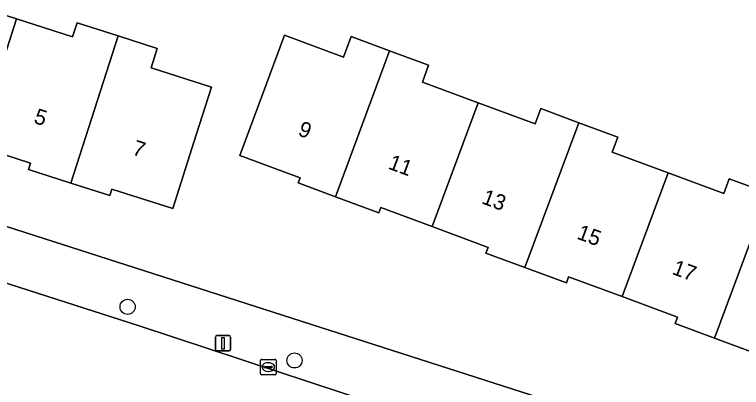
# Model space of a CAD drawing. Extents: x 163266 to 164362, y 381528 to 382286.
# Drawn here: x 163801.11 to 163848.12, y 382001.05 to 382025.18 of the extents above; entities that cross this region are included whole.
import ezdxf

# ---------------------------------------------------------------- set-up
doc = ezdxf.new("R2010")
doc.units = 0
for name, color, linetype in [('IMGEO_Boom', 7, 'Continuous'), ('IMGEO_Erf', 7, 'Continuous'), ('IMGEO_Kolk', 7, 'Continuous'), ('IMGEO_Lichtmast', 7, 'Continuous'), ('IMGEO_Pand', 7, 'Continuous'), ('IMGEO_Pand_nummerreeks', 7, 'Continuous'), ('IMGEO_Rijbaan_lokaal_open', 7, 'Continuous'), ('IMGEO_Voetpad_open', 7, 'Continuous')]:
    doc.layers.add(name, color=color, linetype=linetype)

msp = doc.modelspace()

# ---------------------------------------------------------------- linework, layer by layer
at = {"layer": 'IMGEO_Boom'}
for centre in [(163808.427, 382006.269), (163819.217, 382002.805)]:
    msp.add_circle(centre, 0.489, dxfattribs=at)
at = {"layer": 'IMGEO_Erf'}
for points in [[(163797.866, 382025.977), (163801.242, 382024.894), (163804.871, 382023.73), (163805.164, 382024.644), (163807.816, 382023.794), (163810.342, 382022.984), (163809.942, 382021.739), (163813.86, 382020.482), (163812.869, 382017.392), (163811.342, 382012.63), (163807.414, 382013.889), (163807.279, 382013.469), (163804.764, 382014.276), (163802.025, 382015.154), (163802.156, 382015.564), (163798.615, 382016.7)], [(163848.94, 382003.298), (163846.386, 382004.246), (163843.828, 382005.195), (163843.981, 382005.607), (163840.404, 382006.934), (163836.95, 382008.216), (163836.801, 382007.815), (163834.119, 382008.81), (163831.601, 382009.745), (163831.739, 382010.119), (163828.123, 382011.461), (163824.808, 382012.691), (163824.681, 382012.35), (163821.861, 382013.396), (163819.459, 382014.287), (163819.584, 382014.625), (163815.693, 382016.069), (163817.433, 382020.757), (163818.577, 382023.841), (163822.389, 382022.426), (163822.884, 382023.761), (163825.374, 382022.837), (163827.894, 382021.902), (163827.489, 382020.809), (163831.103, 382019.468), (163834.775, 382018.106), (163835.142, 382019.096), (163837.607, 382018.181), (163840.128, 382017.246), (163839.766, 382016.272), (163843.38, 382014.931), (163846.979, 382013.596), (163847.335, 382014.558), (163849.873, 382013.616)], [(163784.545, 382016.624), (163836.291, 382000), (163875.242, 381987.433)]]:
    msp.add_lwpolyline(points, dxfattribs=at)
at = {"layer": 'IMGEO_Kolk'}
for p, q in [((163817.028, 382001.948), (163817.028, 382002.8)), ((163817.103, 382002.874), (163817.955, 382002.874)), ((163817.516, 382002.654), (163817.541, 382002.654)), ((163818.029, 382002.8), (163818.029, 382001.948)), ((163817.287, 382002.368), (163817.287, 382002.38)), ((163817.725, 382002.331), (163817.327, 382002.331)), ((163817.33, 382002.417), (163817.728, 382002.417)), ((163817.539, 382002.094), (163817.514, 382002.094)), ((163817.771, 382002.38), (163817.771, 382002.368)), ((163817.955, 382001.874), (163817.103, 382001.874))]:
    msp.add_line(p, q, dxfattribs=at)
for points in [[(163817.028, 382001.948), (163817.028, 382002.8)], [(163817.103, 382002.874), (163817.955, 382002.874)], [(163818.029, 382002.8), (163818.029, 382001.948)], [(163817.955, 382001.874), (163817.103, 382001.874)]]:
    msp.add_lwpolyline(points, dxfattribs=at)
for centre, radius, start, end in [((163817.105, 382002.798), 0.0765, 91.552, 178.448), ((163817.105, 382002.798), 0.0765, 91.552, 178.448), ((163817.953, 382002.798), 0.0765, 1.552, 88.448), ((163817.953, 382002.798), 0.0765, 1.552, 88.448), ((163817.327, 382002.377), 0.0403, 85.8775, 175.7526), ((163817.324, 382002.367), 0.0366, 178.938, 274.7102), ((163817.728, 382002.374), 0.043, 264.8664, 352.4533), ((163817.732, 382002.379), 0.0386, 1.7309, 96.639), ((163817.105, 382001.95), 0.0765, 181.552, 268.448), ((163817.105, 382001.95), 0.0765, 181.552, 268.448), ((163817.953, 382001.95), 0.0765, 271.552, 358.448), ((163817.953, 382001.95), 0.0765, 271.552, 358.448)]:
    msp.add_arc(centre, radius, start, end, dxfattribs=at)
for centre, major_axis, ratio, start_param, end_param in [((163817.515, 382002.374), (-0.387, 0.002), 0.722429, 4.712389, 7.853982), ((163817.54, 382002.374), (-0.39, 0.002), 0.717154, 1.570796, 4.712389)]:
    msp.add_ellipse(centre, major_axis=major_axis, ratio=ratio, start_param=start_param, end_param=end_param, dxfattribs=at)
at = {"layer": 'IMGEO_Lichtmast'}
for p, q in [((163814.201, 382004.417), (163814.991, 382004.417)), ((163814.991, 382004.417), (163814.201, 382004.417)), ((163814.101, 382003.517), (163814.101, 382004.317)), ((163814.101, 382004.317), (163814.101, 382003.517)), ((163815.091, 382004.317), (163815.091, 382003.517)), ((163815.091, 382003.517), (163815.091, 382004.317)), ((163814.991, 382003.417), (163814.201, 382003.417)), ((163814.201, 382003.417), (163814.991, 382003.417))]:
    msp.add_line(p, q, dxfattribs=at)
msp.add_lwpolyline([(163814.521, 382004.292), (163814.671, 382004.292), (163814.671, 382003.542), (163814.521, 382003.542), (163814.521, 382004.292)], dxfattribs=at)
for centre, start, end in [((163814.201, 382004.317), 90, 180), ((163814.201, 382004.317), 90, 180), ((163814.991, 382004.317), 0, 90), ((163814.991, 382004.317), 360, 90), ((163814.201, 382003.517), 180, 270), ((163814.201, 382003.517), 180, 270), ((163814.991, 382003.517), 270, 0), ((163814.991, 382003.517), 270, 0)]:
    msp.add_arc(centre, 0.1, start, end, dxfattribs=at)
at = {"layer": 'IMGEO_Pand'}
for points in [[(163801.242, 382024.894), (163797.866, 382025.977), (163798.166, 382026.912), (163795.26, 382027.844), (163792.216, 382018.348), (163794.957, 382017.469), (163795.075, 382017.835), (163798.615, 382016.7)], [(163801.242, 382024.894), (163798.615, 382016.7), (163802.156, 382015.564), (163802.025, 382015.154), (163804.764, 382014.276), (163807.816, 382023.794), (163805.164, 382024.644), (163804.871, 382023.73)], [(163807.816, 382023.794), (163804.764, 382014.276), (163807.279, 382013.469), (163807.414, 382013.889), (163811.342, 382012.63), (163812.869, 382017.392), (163813.86, 382020.482), (163809.942, 382021.739), (163810.342, 382022.984)], [(163821.861, 382013.396), (163825.374, 382022.837), (163822.884, 382023.761), (163822.389, 382022.426), (163818.577, 382023.841), (163817.433, 382020.757), (163815.693, 382016.069), (163819.584, 382014.625), (163819.459, 382014.287)], [(163828.123, 382011.461), (163831.103, 382019.468), (163827.489, 382020.809), (163827.894, 382021.902), (163825.374, 382022.837), (163821.861, 382013.396), (163824.681, 382012.35), (163824.808, 382012.691)], [(163828.123, 382011.461), (163831.739, 382010.119), (163831.601, 382009.745), (163834.119, 382008.81), (163837.607, 382018.181), (163835.142, 382019.096), (163834.775, 382018.106), (163831.103, 382019.468)], [(163840.404, 382006.934), (163843.38, 382014.931), (163839.766, 382016.272), (163840.128, 382017.246), (163837.607, 382018.181), (163834.119, 382008.81), (163836.801, 382007.815), (163836.95, 382008.216)], [(163846.386, 382004.246), (163849.873, 382013.616), (163847.335, 382014.558), (163846.979, 382013.596), (163843.38, 382014.931), (163840.404, 382006.934), (163843.981, 382005.607), (163843.828, 382005.195)], [(163846.386, 382004.246), (163848.94, 382003.298), (163849.082, 382003.679), (163852.662, 382002.351), (163855.655, 382010.392), (163852.013, 382011.743), (163852.365, 382012.692), (163849.873, 382013.616)]]:
    msp.add_lwpolyline(points, close=True, dxfattribs=at)
at = {"layer": 'IMGEO_Rijbaan_lokaal_open'}
msp.add_lwpolyline([(163849.853, 381991.631), (163831.384, 381997.714), (163809.167, 382005.041), (163762.591, 382019.997), (163757.318, 382021.706), (163755.403, 382022.326), (163754.211, 382022.697), (163752.053, 382015.936), (163753.214, 382015.593), (163756.256, 382014.586), (163765.277, 382011.726), (163801.005, 382000.175), (163801.506, 382000), (163801.743, 381999.917), (163803.998, 381999.189)], dxfattribs=at)
at = {"layer": 'IMGEO_Voetpad_open'}
msp.add_lwpolyline([(163836.291, 382000), (163784.545, 382016.624), (163783.143, 382017.074), (163773.431, 382020.194), (163770.69, 382021.032), (163765.086, 382022.744), (163758.349, 382025.147), (163757.318, 382021.706), (163762.591, 382019.997), (163809.167, 382005.041), (163831.384, 381997.714), (163849.853, 381991.631), (163896.886, 381976.383)], dxfattribs=at)

# ---------------------------------------------------------------- texts
at = {"layer": 'IMGEO_Pand_nummerreeks'}
for s, rotation, p in [('5', 342.1892, (163802.304, 382018.18)), ('9', 339.6423, (163819.388, 382017.385)), ('7', 342.1892, (163808.668, 382016.135)), ('11', 339.6423, (163825.219, 382015.222)), ('13', 339.6423, (163831.267, 382012.978)), ('15', 339.6423, (163837.422, 382010.694)), ('17', 339.6423, (163843.577, 382008.411))]:
    msp.add_text(s, height=1, rotation=rotation, dxfattribs=at).set_placement(p)

doc.saveas('drawing.dxf')
